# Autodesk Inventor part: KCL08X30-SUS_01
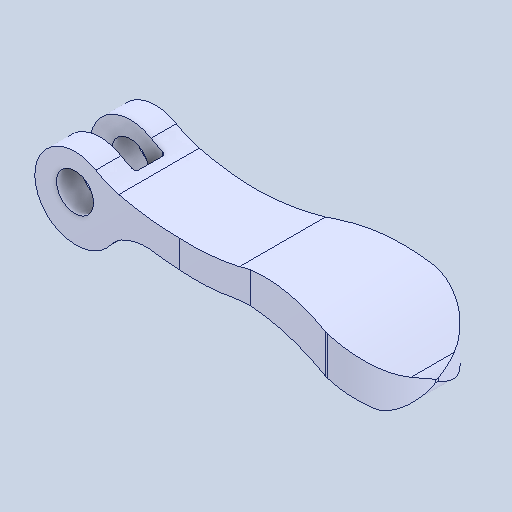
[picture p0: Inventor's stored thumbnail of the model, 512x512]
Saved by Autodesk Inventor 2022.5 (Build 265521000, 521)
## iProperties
Created: 2024-08
Part Number: KCL08X30-SUS_01
Material: 一般
Document SubType Name: Modeling
Designer: ImaoCorp
Density: 1 g/cm^3
Appearance: 既定
Author: ImaoCorp
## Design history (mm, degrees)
feature "KCL08X30-SUS_01"
node "ソリッド1"
